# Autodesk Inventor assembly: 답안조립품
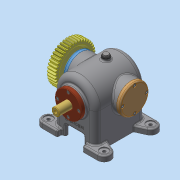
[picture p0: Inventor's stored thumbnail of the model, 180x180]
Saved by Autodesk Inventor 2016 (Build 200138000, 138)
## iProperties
Created: 2024-09
Part Number: 답안조립품
Material: 일반
Document SubType Name: Assembly
Designer: pc-7
Author: pc-7
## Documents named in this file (17)
- C:\Users\pc-7\Desktop\740904V1020\답안조립품.iam
- C:\Users\pc-7\Desktop\740904V1020\본체.ipt
- C:\Users\pc-7\Desktop\740904V1020\가져온 구성요소\뒷커버\뒷커버.ipt
- C:\Users\pc-7\Desktop\740904V1020\가져온 구성요소\앞커버\앞커버.ipt
- C:\Users\pc-7\Desktop\740904V1020\가져온 구성요소\부시\부시.ipt
- C:\Users\pc-7\Desktop\740904V1020\가져온 구성요소\깊은 홈 볼베어링 6203\깊은 홈 볼베어링 6203.ipt
- C:\Users\pc-7\Desktop\740904V1020\가져온 구성요소\편심축\편심축.ipt
- C:\Users\pc-7\Desktop\740904V1020\가져온 구성요소\오일실 17 32 8\오일실 17 32 8.ipt
- C:\Users\pc-7\Desktop\740904V1020\가져온 구성요소\육각 소켓 머리 볼트 M4x10\육각 소켓 머리 볼트 M4x10.ipt
- C:\Users\pc-7\Desktop\740904V1020\가져온 구성요소\평행키 3x3x14\평행키 3x3x14.ipt
- C:\Users\pc-7\Desktop\740904V1020\가져온 구성요소\스퍼 기어\스퍼 기어.ipt
- C:\Users\pc-7\Desktop\740904V1020\가져온 구성요소\평와셔 M10\평와셔 M10.ipt
- C:\Users\pc-7\Desktop\740904V1020\가져온 구성요소\스프링와셔 M10\스프링와셔 M10.ipt
- C:\Users\pc-7\Desktop\740904V1020\가져온 구성요소\육각 너트 M10x1\육각 너트 M10x1.ipt
- C:\Users\pc-7\Desktop\740904V1020\가져온 구성요소\로드\로드.ipt
- C:\Users\pc-7\Desktop\740904V1020\가져온 구성요소\실링 패드\실링 패드.ipt
- C:\Users\pc-7\Desktop\740904V1020\가져온 구성요소\육각 머리 볼트 M6x0.75x12\육각 머리 볼트 M6x0.75x12.ipt
